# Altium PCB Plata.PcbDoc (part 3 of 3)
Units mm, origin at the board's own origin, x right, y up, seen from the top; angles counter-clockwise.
Board outline 225.2 x 126.25 mm, 5 copper layers (Top Layer, Mid-Layer 1, Mid-Layer 2, Mid-Layer 3, Bottom Layer); 204 components, 178 nets, 840 pads, 262 vias.
Unrouted connection lines stored in the file: 7.
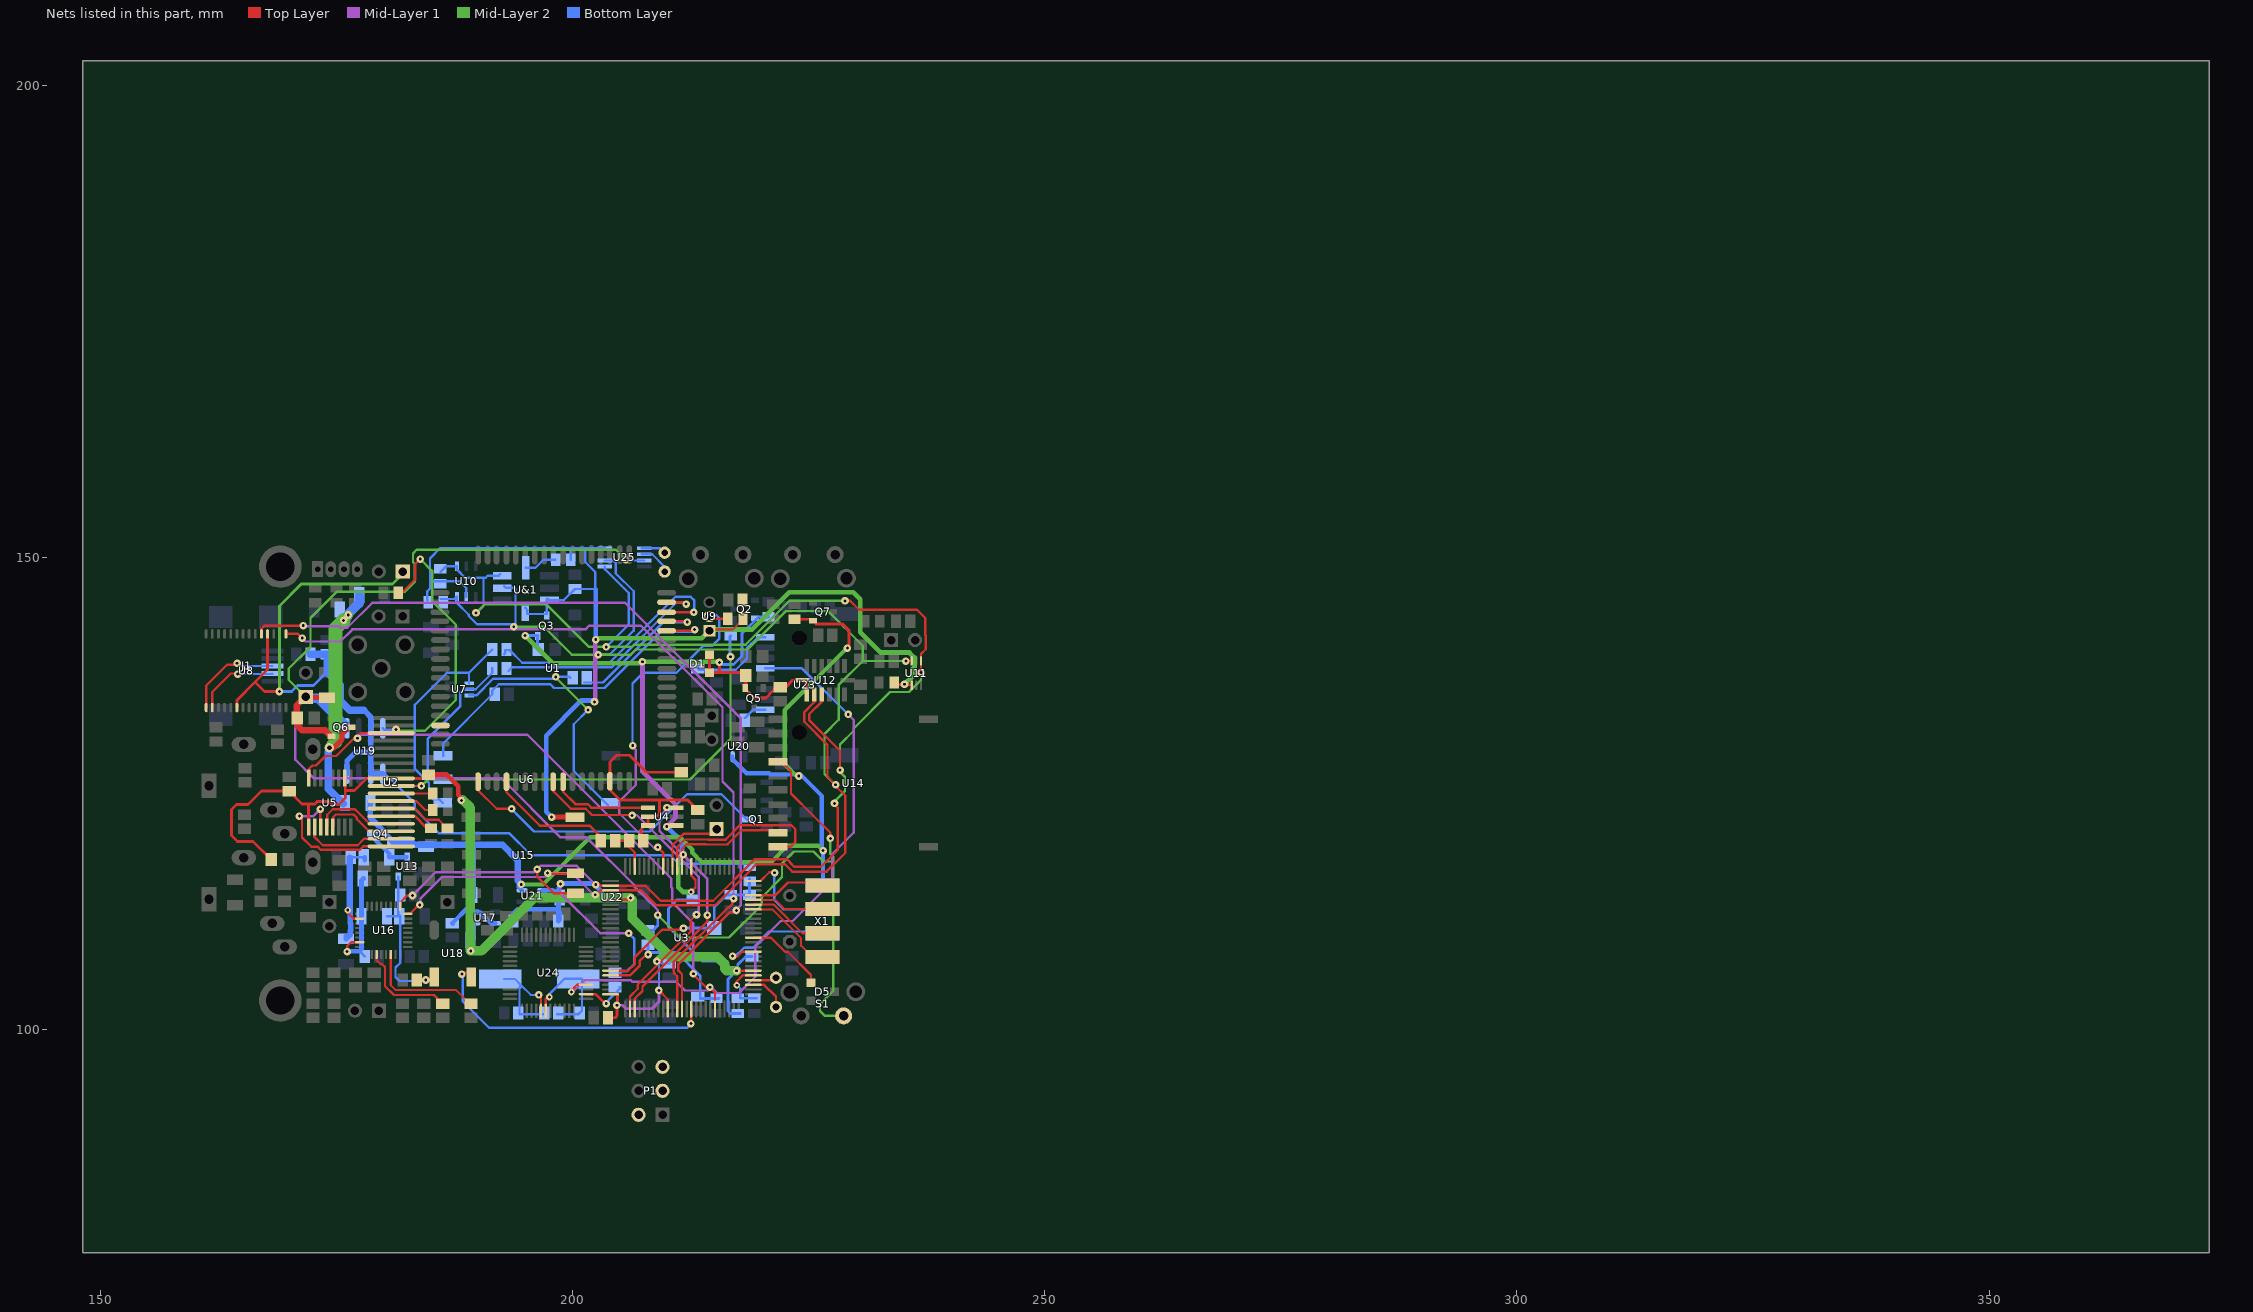
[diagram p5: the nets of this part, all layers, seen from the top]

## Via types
v1: diameter 0.8, hole 0.3, Top Layer to Bottom Layer, 158 vias
v2: diameter 0.8, hole 0.3, Top Layer to Mid-Layer 1, 69 vias
v3: diameter 0.8, hole 0.3, Mid-Layer 2 to Bottom Layer, 18 vias
v4: diameter 0.7, hole 0.3, Top Layer to Bottom Layer, 9 vias
v5: diameter 0.7, hole 0.3, Top Layer to Mid-Layer 1, 5 vias
v6: diameter 0.8, hole 0.3, Top Layer to Mid-Layer 1, tented top, 1 vias
v7: diameter 0.8, hole 0.3, Top Layer to Bottom Layer, tented top, 1 vias
v8: diameter 1, hole 0.5, Top Layer to Bottom Layer, 1 vias

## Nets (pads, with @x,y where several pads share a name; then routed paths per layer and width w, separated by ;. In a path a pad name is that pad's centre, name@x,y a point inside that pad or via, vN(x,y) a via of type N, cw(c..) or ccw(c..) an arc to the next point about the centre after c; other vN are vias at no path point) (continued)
NetR13_2: R13.2 U2.11 | length 4.4
  Top Layer w0.25: U2.11@180.8,125 R13.2@185.2,125
NetR14_2: R14.2 U2.12 | length 4.8
  Top Layer w0.25: U2.12@180.8,124.2 183.45,124.2 184.4,123.25 R14.2@185.2,123.25
NetR15_2: R15.2 U2.13 | length 6.8
  Top Layer w0.25: U2.13@180.8,123.4 183.3,123.4 184.475,122.225 185.825,122.225 R15.2@186.75,121.3
NetR16_2: R16.2 U2.14 | length 4.7
  Top Layer w0.25: U2.14@180.8,122.6 183.3,122.6 184.6,121.3 R16.2@185,121.3
NetR17_1: R17.1 U2.10 | length 49
  Top Layer w0.25: U2.10@180.8,125.8 v1(184,125.8)
  Mid-Layer 2 w0.25: v1(184,125.8) 184.675,126.475 212.425,126.475 216.725,130.775 216.725,139.175 v3@216.875,139.325
  Bottom Layer w0.3: R17.1@216.75,141.7 216.675,141.625 216.675,139.75 216.837,139.588 v3@216.95,139.475
  other v3: 216.725,139.475
NetR24_1: R24.1 U6.4 U7.6 | length 28.7
  Mid-Layer 2 w0.25: v3(198.225,137.35) 198.225,137.275 v3@201.475,134.025
  Bottom Layer w0.25: U7.6@189.04,135.39 189.815,135.39 191.575,137.15 198.125,137.15 v3@198.225,137.25 ; R24.1@199.75,137.25 199.65,137.35 v3@198.325,137.35 ; v3(201.65,133.85) 200.125,132.325 200.125,127.375 U6.4@203.75,123.75 ; v3@198.225,137.25 198.275,137.3 v3@198.325,137.35 ; v3@198.225,137.25 v3(198.225,137.35) v3@198.325,137.35
NetR26_1: R26.1 U6.3 U7.4 | length 23.7
  Bottom Layer w0.25: U6.3@186.25,124 185.85,124.4 185.225,124.4 184.8,124.825 184.8,126.096 183.3,127.596 183.3,134.4 186.69,137.79 189.04,137.79 ; U7.4@189.04,136.68 189.04,137.79 ; R26.1@191.5,140.25 189.04,137.79
NetR27_1: R27.1 U6.2 U7.5 | length 16.5
  Bottom Layer w0.25: U6.2@186.404,126.604 186.257,126.75 185.275,126.75 184.65,127.375 184.65,130.775 188.125,134.25 188.125,135.705 188.45,136.03 U7.5@189.04,136.03 189.748,136.03 191.5,137.782 R27.1@191.5,138.25
NetR29_1: R29.1 U&1.8 | length 3.5
  Bottom Layer w0.25: U&1.8@195.05,148.9 196.075,148.9 196.925,149.75 R29.1@198.2,149.75
NetR44_2: R44.2 U19.8 | length 30.5
  Top Layer w0.25: R44.2@181.55,146.25 181.95,146.25 183.325,147.625 183.325,149.275 v1(183.875,149.825)
  Mid-Layer 2 w0.25: v3@181.425,131.625 184.35,131.625 187.625,134.9 187.625,142.9 185.125,145.4 185.125,148.575 v1(183.875,149.825)
  Bottom Layer w0.25: U19.8@179.905,131.9 180.055,131.75 181.3,131.75 v3@181.525,131.75
  other v3: 181.3,131.775
NetR54_2: R54.2 U23.1 | length 2.5
  Bottom Layer w0.25: R54.2@218.25,133 219.1,133.85 U23.1@220.4,133.85
NetR55_2: R55.2 U23.8 | length 9.3
  Bottom Layer w0.25: R55.2@213.25,138.25 213.4,138.1 217.275,138.1 218.475,139.3 218.475,140.405 219.62,141.55 U23.8@220.4,141.55
NetR57_2: R57.2 U24.26 | length 5
  Top Layer w0.25: U24.26@201.425,103.75 202.425,103.75 203.375,102.8 v1@203.575,102.8 ; v1(203.575,102.758) v1@203.575,102.8 ; v1@203.8,102.8 v1@203.575,102.8
  Bottom Layer w0.25: v1@203.8,102.8 203.8,103.125 204.837,104.162 205,104.325 R57.2@205,104.5
NetU2_15: U2.15 U5.4 | length 9.5
  Top Layer w0.25: U5.4@173.932,120.9 173.932,121.425 173.957,121.45 174.025,121.517 174.025,122.75 174.6,123.325 176.962,123.325 178.487,121.8 U2.15@180.8,121.8
NetU2_16: U2.16 U5.5 | length 8.8
  Top Layer w0.25: U5.5@174.567,120.9 U5.5@174.567,121.4 ; U5.5@174.657,121.49 174.605,121.437 U5.5@174.567,121.4 ; U2.16@180.8,121 178.45,121 177.137,122.313 177.137,122.442 176.805,122.775 174.925,122.775 174.65,122.5 174.65,121.507 174.592,121.45 174.567,121.425 U5.5@174.567,121.4
NetU2_17: U2.17 U5.2 | length 9.3
  Top Layer w0.25: U5.2@172.662,120.9 172.662,120.406 173.544,119.525 177.25,119.525 177.925,120.2 U2.17@180.8,120.2
NetU2_18: U2.18 U5.3 | length 16.8
  Top Layer w0.25: v2@171.35,122.5 171.35,120.347 172.322,119.375 172.987,119.375 173.337,119.025 177.457,119.025 177.832,119.4 U2.18@180.8,119.4 ; U5.3@173.297,121.4 173.297,121.425 v2(173.297,123.347) v2@173.3,123.35
  Mid-Layer 1 w0.25: v2(171.075,122.6) 172.55,122.6 v2(173.297,123.347)
NetU3_28: U3.28 Y1.2 | length 4
  Top Layer w0.25: U3.28@219.136,104.736 220.289,104.736 221.538,103.487 Y1.2@221.538,102.387
NetU3_29: U3.29 Y1.1 | length 2.2
  Top Layer w0.25: U3.29@219.136,105.236 220.936,105.236 Y1.1@221.25,105.55
NetU25_1: U25.1 Y4.2 | length 2.6
  Bottom Layer w0.25: U25.1@207.325,150.975 U25.1@207.575,150.975 209.275,150.975 Y4.2@209.75,150.5
NetU25_2: U25.2 Y4.1 | length 3.5
  Bottom Layer w0.25: U25.2@207.325,150.325 U25.2@207.575,150.325 208.43,150.325 209.75,149.005 Y4.1@209.75,148.5
PIN1_OUT: U3.47 X1.1 | length 8.3
  Top Layer w0.22: X1.1@225.15,115.75 225.95,115.75 X1.1@226.45,115.25
  Top Layer w0.25: U3.47@219.136,114.236 220.114,114.236 ; U3.47@219.975,114.236 221.486,114.236 222.825,115.575 224.975,115.575 X1.1@225.15,115.75
PIN2_OUT: U3.44 X1.4 | length 9.9
  Top Layer w0.22: U3.44@219.136,112.736 221.133,112.736 224.2,109.669 224.2,108.875 225.375,107.7 X1.4@226.45,107.7
PIN3_OUT: U3.35 X1.7 | length 12.9
  Top Layer w0.24: v1(216.95,107.775) 217.489,107.775 217.95,108.236 U3.35@219.136,108.236
  Bottom Layer w0.24: v1@217.125,107.675 217.152,107.675 218.147,108.67 219.07,108.67 220.78,110.38 226.27,110.38 X1.7@226.45,110.2
PIN4_OUT: U3.50 X1.6 | length 11
  Top Layer w0.25: U3.50@219.136,115.736 219.911,115.736 220.825,116.65 v1@221.4,116.65
  Bottom Layer w0.25: v1@221.35,116.525 221.35,113.725 222.325,112.75 X1.6@226.45,112.75 ; v1@221.375,116.625 v1@221.4,116.65
  other v1: 221.4,116.6
POWER_ON: D5.1 U3.38 | length 8.6
  Top Layer w0.25: U3.38@219.136,109.736 220.994,109.736 222.495,108.235 222.79,108.235 225.25,105.775 D5.1@225.25,104.95
PWRKEY: Q1.3 U1.1 | length 33.8
  Top Layer w0.25: U1.1@190,126.25 190,125.35 191.975,123.375 v1(193.55,123.375)
  Bottom Layer w0.25: v1@193.637,123.237 195.9,120.975 208.175,120.975 212.125,124.925 215.775,124.925 Q1.3@218.45,122.25
RADIO_L_LINE: C29.2 U16.3 | length 10.9
  Top Layer w0.22: C29.2@185.72,102.75 C29.2@185.72,102.997
  Top Layer w0.24: U16.3@179.25,107.95 179.25,107.345 179.675,106.92 179.853,106.92 180.15,106.623 180.15,104.6 181.08,103.67 185.33,103.67 C29.2@186.25,102.75
RADIO_R_LINE: C30.2 U16.6 | length 12.6
  Top Layer w0.22: U16.6@180.75,107.95 180.75,106.85 180.75,104.7 181.275,104.175 187.675,104.175 189.1,102.75 C30.2@189.25,102.75
RESET: C1.2 P1.3 R3.1 U3.30 | length 6.6
  Top Layer w0.25: v4(217.4,104.7) 217.4,105.125 218.011,105.736 U3.30@219.136,105.736 218.196,105.736
  Bottom Layer w0.25: v4(217.4,104.7) 217.75,104.35 217.75,103.3 C1.2@219.25,103.3 C1.2@219.5,103.3
RING: R9.1 U1.4 | length 13.8
  Top Layer w0.25: U1.4@193,126.25 193,125.125 196.525,121.6 201.8,121.6 203,120.4 R9.1@203,120 R9.1@203,119.75 ; R9.1@202.695,119.805 R9.1@202.75,119.75
RING_CPU: R9.2 R10.1 U3.73 | length 4.2
  Top Layer w0.25: R9.2@204.25,119.75 R9.2@204.5,119.75 ; R9.2@204.5,120 R10.1@205.75,120 ; R10.1@206,119.75 206,119.325 206.586,118.739 U3.73@206.586,117.286
RXD_GPS: U3.63 U14.9 | length 12.9
  Top Layer w0.25: U3.63@211.586,117.286 211.586,119.119 212.087,119.62 212.154,119.62 212.164,119.631 214.112,119.631 214.138,119.605 216.362,119.605 216.377,119.62 216.423,119.62 217.903,121.1 221.5,121.1 U14.9@221.75,120.85
RXD_GSM_CPU: U1.9 U3.2 | length 37.5
  Top Layer w0.25: U1.9@197.95,126.25 197.95,125.25 199.825,123.375 201.405,123.375 202.055,122.725 v2@206.3,122.725 ; U3.2@206.086,102.186 206.086,103.13 ; 206.086,103.357 206.086,103.13 ; v2(213.125,112.175) 212.525,111.575 212.525,110.396 206.9,104.771 206.9,104.325 206.086,103.511 206.086,103.13
  Mid-Layer 1 w0.25: v2@205.975,122.725 206.3,122.725 206.8,122.725 211.21,118.315 211.21,118.303 211.957,117.556 211.969,117.556 213.35,116.175 213.35,112.425 v2@213.25,112.325
  other v2: 206.3,122.675
RXD_OUT: U3.45 X1.3 | length 8.6
  Top Layer w0.22: U3.45@219.136,113.236 221.255,113.236 221.285,113.206 221.328,113.206 224.334,110.2 X1.3@226.45,110.2
RXD_USB: U3.13 U8.5 | length 91.9
  Top Layer w0.25: U8.5@167.05,141.9 167.05,142.45 167.375,142.775 v1(171.475,142.775) ; U3.13@211.586,102.186 211.586,105.86 211.205,106.241 211.205,106.955 216.688,112.438 217.138,112.438 v2@217.138,112.625
  Mid-Layer 1 w0.25: v1(171.475,142.775) 171.6,142.65 171.65,142.7 175.279,142.7 175.429,142.55 176.15,142.55 178.8,145.2 205.561,145.2 217.825,132.936 217.825,113.175 217.525,112.875 217.525,112.625 217.525,112.45 v2@217.4,112.325
  other v2: 217.35,112.625
SCK: P1.2 U2.3 U3.20 U5.16 U23.5 U24.28 | length 134.5
  Top Layer w0.25: U5.16@172.027,126.6 172.065,126.637 U5.16@172.097,126.67 ; U5.16@172.117,126.69 U5.16@172.097,126.67 ; U2.3@180.8,131.4 177.6,131.4 177.137,130.938 176.912,130.712 176.725,130.712 174.983,128.97 173.832,128.97 172.827,127.965 172.447,127.965 172.097,127.615 U5.16@172.097,126.67 ; v5@199.775,104 199.812,104.037 200.195,104.42 200.195,104.463 200.482,104.75 U24.28@201.425,104.75 ; v2(212.8,105.91) 212.8,105.9 212.75,105.85 214.125,104.475 v1(214.55,104.475) ; v1@214.7,104.325 214.688,104.313 215.086,103.914 U3.20@215.086,102.186
  Mid-Layer 1 w0.25: v2(177.225,130.85) 177.6,131.225 195.218,131.225 210.45,115.993 210.45,115.079 210.575,114.954 210.575,113.45 212.785,111.24 212.785,105.995 212.75,105.96 212.75,105.95 212.79,105.91 v2(212.8,105.91) ; v5@199.775,104 199.875,104 200.046,104 201.253,105.207 206.188,105.207 206.325,105.07 209.974,105.07 209.979,105.075 210.621,105.075 210.626,105.07 210.962,105.07 211.897,104.135 214.36,104.135 214.625,104.4 214.775,104.4 215.3,103.875 217.632,103.875 219.35,105.593 219.35,108.772 219.675,109.097 219.675,109.128 222.047,111.5 223.318,111.5 227.5,115.682 227.5,118.582 229.775,120.857 229.775,132.77 229.22,133.325 229.19,133.368 v1@229.145,133.43 ; v5@199.775,104.075 v5@199.805,104.045
  Bottom Layer w0.25: U23.5@220.4,138.25 224.3,138.25 229.05,133.5 229.05,133.375 v1@229.05,133.25
  other v1: 229.2,133.375
  other v5: 199.875,103.975
SCL: R11.1 U3.78 U10.6 U11.6 U12.2 U15.2 U16.16 U25.6 U&1.6 | length 167.2
  Top Layer w0.25: U16.16@182.55,112.25 182.75,112.25 v2@183.512,113.012 ; v2@197.625,116.5 200.25,116.5 U15.2@200.3,116.55 ; v2(202.4,114.275) 202.429,114.275 202.579,114.425 202.65,114.425 202.961,114.736 U3.78@204.036,114.736 207.289,114.736 208.875,113.15 215.107,113.15 219.202,117.245 ; 219.206,117.241 219.49,117.525 222.472,117.525 223.272,116.725 226.9,116.725 228.875,118.7 228.875,124.775 227.825,125.825 v1@227.825,125.9 ; U12.2@225.6,135.5 225.6,134.675 224.55,133.625 224.55,132.589 227,130.139 227,126.725 v1@227.825,125.9 ; v1(227.861,125.931) 227.856,125.931 v1@227.825,125.9 ; v1@235.395,139.025 235.42,139.05 U11.6@235.9,139.05
  Mid-Layer 1 w0.25: v2(183.809,113.206) 183.894,113.206 183.9,113.2 183.9,113.206 183.9,113.875 186.175,116.15 197.125,116.15 v2@197.45,116.475 ; v2(197.35,116.575) 199.95,116.575 202.25,114.275 v2@202.25,114.15
  Mid-Layer 2 w0.25: v3(193.775,142.65) 197.021,142.65 197.021,142.608 199.929,139.7 v3(202.725,139.7) 206.15,139.7 206.7,140.25 218.532,140.25 222.607,144.325 227.037,144.325 230.721,140.64 230.721,139.025 ; v1(227.861,125.931) 227.856,125.931 227.825,125.9 226.675,127.05 226.675,131.314 228.175,132.814 228.175,136.479 230.721,139.025 ; v1@235.395,139.025 v1(235.3,139.025) 230.721,139.025
  Bottom Layer w0.25: R11.1@186.05,145.6 186.3,145.6 187.5,145.6 U10.6@187.75,145.85 187.75,145.175 189,143.925 189,143.804 189.879,142.925 193.775,142.925 v3@193.95,142.925 ; U&1.6@192.75,146.95 192.925,146.775 193.85,146.775 193.95,146.675 v3@193.95,142.925 ; v3@193.97,142.905 v3@193.95,142.925 ; v3(202.725,139.7) 203.925,139.7 206.475,142.25 206.475,146.407 204.575,148.307 204.575,149.38 204.28,149.675 U25.6@203.425,149.675
SDA: R12.1 U3.77 U10.1 U11.4 U12.3 U15.1 U16.17 U25.5 U&1.7 | length 173.2
  Top Layer w0.25: U16.17@181.75,113.05 181.75,113.475 182.475,114.2 v2(183.05,114.2) ; v2@196.245,116.975 196.245,116.205 198,114.45 U15.1@200.3,114.45 ; v2(202.45,115.35) 202.8,115.35 202.914,115.236 U3.77@204.036,115.236 207.739,115.236 209.325,113.65 214.9,113.65 219.275,118.025 222.732,118.025 223.025,117.732 223.025,117.679 223.479,117.225 226.275,117.225 228.075,119.025 228.075,123.475 227.665,123.885 v1@227.5,124.05 ; U12.3@226.4,135.5 226.4,134.75 225.05,133.4 225.05,132.796 228.325,129.521 228.325,127.575 228.275,127.525 228.225,127.475 v7@228.225,127.325 ; v1(228.85,145.4) 229.4,145.4 230.35,144.45 236.475,144.45 237.365,143.56 237.365,141.746 237.395,141.716 237.395,140.27 236.9,139.775 U11.4@236.9,139.05 v1(236.9,137.8) v1@236.9,137.6
  Mid-Layer 1 w0.25: v2(183.05,114.2) 185.5,116.65 195.925,116.65 v2@196.05,116.775 ; v2@196.461,117.211 196.6,117.35 200.425,117.35 v2@202.437,115.338
  Mid-Layer 2 w0.25: v3(189.775,144.125) 190.675,145.025 197.25,145.025 201.75,140.525 v3(203.575,140.525) 206.268,140.525 206.493,140.75 218.325,140.75 223,145.425 228.625,145.425 228.75,145.3 v1@228.85,145.2 ; v1@227.675,124.1 228.85,125.275 228.85,126.75 v7@228.225,127.375 ; v7@228.325,127.325 v7(228.325,127.475) 228.325,130.2 229.775,131.65 229.775,131.896 233.629,135.75 235.625,135.75 236.9,137.025 v1(236.9,137.8)
  Bottom Layer w0.25: R12.1@186.05,148.5 186.175,148.625 186.6,149.05 U10.1@187.75,149.05 187.75,148.725 188.625,147.85 190.8,147.85 191.025,148.075 192.175,148.075 U&1.7@192.35,148.25 ; v3@189.85,144.125 190.575,144.85 190.575,147.825 ; U25.5@203.425,149.025 203.425,148.75 205.95,146.225 205.95,142.9 v3(203.575,140.525)
  other v1: 227.736,123.956
  other v2: 196.25,116.975
SIM_CLK: R26.2 U1.32 | length 28.2
  Top Layer w0.25: U1.32@209.95,144.2 v1@212.75,144.2
  Bottom Layer w0.25: R26.2@192.762,139.763 192.875,139.875 192.875,140.2 193,140.2 193.325,140.2 194.675,138.85 203.925,138.85 210.9,145.825 212.504,145.825 212.9,145.429 212.9,144.33 212.798,144.227 v1@212.77,144.2
  other v1: 212.825,144.2
SIM_DATA: R24.2 U1.31 | length 15.7
  Top Layer w0.25: U1.31@209.95,143.25 v1@212.125,143.25
  Bottom Layer w0.25: R24.2@201.25,136.75 201.5,136.75 203.239,136.75 209.639,143.15 v1(212.15,143.15)
SIM_RESET: R27.2 U1.33 | length 23.9
  Top Layer w0.25: U1.33@209.95,145.25 212.025,145.25 212.01,145.235 v1@212.01,145.207
  Bottom Layer w0.25: R27.2@193.25,138 193.6,138.35 204.132,138.35 211.032,145.25 211.967,145.25 v1@212.01,145.207
  other v1: 212.025,145.05
SIM_VDD: C13.2 U1.30 U6.1 | length 36.2
  Top Layer w0.25: U1.30@209.95,142.25 v1@212.925,142.25
  Bottom Layer w0.25: U6.1@186.3,129 186.3,130.3 191.5,135.5 191.5,135.9 192.175,136.575 197.65,136.575 198.05,136.175 203.371,136.175 209.296,142.1 v1@212.8,142.1
  other v1: 212.925,142.35
STATUS: U1.66
TEMP: R28.2 U3.67 U9.2 | length 39.1
  Top Layer w0.25: v1(209.025,119.3) 209.586,118.739 U3.67@209.586,117.286 ; U9.2@214.5,144 214.625,143.875 215,143.5 R28.2@216.45,143.5
  Mid-Layer 1 w0.25: v1@206.25,130.1 206.325,130.025 206.7,129.65 206.7,125.9 204.95,124.15 204.95,122.907 208.657,119.2 v1@208.925,119.2
  Bottom Layer w0.25: v1@206.35,130.075 206.35,136.65 207.475,137.775 210.975,137.775 213.825,140.625 214.775,140.625 215.55,141.4 215.55,143.55 215.1,144 U9.2@214.5,144
  other v1: 206.375,130.075
TXD_GPS: U3.64 U14.10 | length 19.1
  Top Layer w0.25: U3.64@211.086,117.286 211.086,119.326 211.88,120.12 211.946,120.12 211.957,120.131 214.319,120.131 214.345,120.105 216.155,120.105 216.17,120.12 216.216,120.12 217.746,121.65 223.15,121.65 223.575,121.225 223.575,119.85 223.075,119.35 U14.10@221.75,119.35
TXD_GSM: U1.10 U4.4 | length 10.8
  Top Layer w0.25: U1.10@199,126.25 199,125.175 200.3,123.875 201.612,123.875 201.987,123.5 U4.4@208,123.5
TXD_GSM_CPU: U3.3 U4.3 | length 28
  Top Layer w0.25: 206.586,103.193 U3.3@206.586,102.186 206.586,103.286 207.4,104.1 207.4,104.564 214.275,111.439 v2(214.275,112.125)
  Mid-Layer 1 w0.25: v2(210,123.5) 210,123.35 209.2,122.55 209.2,121.032 211.71,118.522 211.71,118.51 212.164,118.056 212.176,118.056 214.275,115.957 v2(214.275,112.125) v2@214.275,112.025
TXD_OUT: U3.46 X1.2 | length 7.7
  Top Layer w0.22: U3.46@219.136,113.736 221.42,113.736 221.48,113.676 221.522,113.676 222.448,112.75 X1.2@226.45,112.75
TXD_USB: U3.12 U8.1 | length 86
  Top Layer w0.25: U8.1@169.65,141.9 170.925,141.9 v1(171.375,141.45) ; U3.12@211.086,102.186 211.086,105.653 210.705,106.034 210.705,107.162 216.481,112.938 216.563,112.938 216.9,113.275 v2@216.9,113.875
  Mid-Layer 1 w0.25: v1(171.375,141.45) 171.725,141.1 175.407,141.1 176.682,142.375 201.358,142.375 201.758,142.775 207.23,142.775 215.875,134.13 215.875,126.275 217.05,125.1 v2(217.05,113.875)
U_BAT_CONTROL: C11.2 R21.2 R25.1 U3.96 | length 17
  Top Layer w0.25: U3.96@204.036,105.736 206.093,105.736 207.1,106.743 207.1,107.25 v1@207.75,107.9
  Bottom Layer w0.3: R21.2@208,109 v1(208,107.95) 208.2,108.15 211.05,108.15 213.525,105.675 213.525,103.5 213.525,103.275 215.25,103.275 215.475,103.275 R25.1@215.525,103.325
U_IN_CONTROL: C61.1 D4.2 R46.1 R49.2 U3.95 | length 21.6
  Top Layer w0.25: U3.95@204.036,106.236 205.886,106.236 206.6,106.95 206.6,107.7 209.475,110.575 v1@211.75,110.575
  Top Layer w0.3: v1@211.75,110.575 v1@211.9,110.575
  Bottom Layer w0.3: v1@211.75,110.75 D4.2@215,110.75 215,112.975 216.275,114.25 216.75,114.25 C61.1@218.75,114.25 R46.1@218.75,115.7 R46.1@218.75,115.95
  other v1: 211.75,110.725
USB+: J1.3 U8.15 | length 10.4
  Top Layer w0.25: U8.15@161.2,134.1 161.2,136.425 163.425,138.65 v1@164.475,138.65
  Bottom Layer w0.25: v1(164.475,138.8) 164.775,138.5 J1.3@168.213,138.5
USB-: J1.2 U8.16 | length 8.7
  Top Layer w0.25: U8.16@161.85,134.1 161.85,135.75 163.8,137.7 v1@164.425,137.7
  Bottom Layer w0.25: v1(164.525,137.65) 168.163,137.65 J1.2@168.213,137.7
VBAT: BT1.1 C62.1 Q6.2 R21.1 R43.1 S1.2 U14.4 U19.5 U25.3 | length 179.5
  Top Layer w0.25: U14.4@221.75,128.35 222.13,128.35 223.125,127.355 223.125,125.012 ; 223.2,124.937 223.125,125.012 ; v1(227.3,120.25) 227.3,120.844 225.494,122.65 225.487,122.65 223.125,125.012
  Top Layer w0.3: R43.1@170.8,132.95 170.725,132.875 170.85,132.75 170.85,132.2
  Top Layer w0.55: BT1.1@171.75,135.23 171.83,135.15 C62.1@174,135.15
  Top Layer w0.7: R43.1@170.8,132.95 170.8,133 170.8,134.35 171.575,135.125 171.575,135.23 BT1.1@171.575,135.275 ; 170.85,132.2 171.37,131.68 173.82,131.68 Q6.2@174.45,131.05
  Mid-Layer 1 w0.25: BT1.1@171.75,135.23 170.65,134.13 170.65,128.572 172.522,126.7 ; 172.66,126.605 192.484,126.605 198.739,120.35 201.478,120.35 206.6,115.228 206.6,115.075 209.025,112.65 v1(209.025,112.125)
  Mid-Layer 1 w0.3: 172.522,126.7 172.565,126.7 172.66,126.605
  Mid-Layer 2 w0.25: BT1.1@171.75,135.23 169.95,137.03 169.95,138.22 172.25,140.52 172.25,143.6 175,146.35 182.225,146.35 183.275,147.4 183.275,149.329 183.1,149.504 183.1,150.425 183.5,150.825 204.575,150.825 v3(205.65,149.75) ; v1(209.025,112.125) 211.4,109.75 216.571,109.75 220.025,113.204 220.025,114 222.175,116.15 222.175,117.575 223.457,118.857 225.522,118.857 226.579,117.8 227.625,117.8 ; v1(227.3,120.25) 227.3,118.629 227.625,118.304 227.625,117.8 ; 227.6,104.354 227.6,104.1 ; S1.2@228.7,101.45 226.725,101.45 226.2,101.975 226.2,102.7 227.6,104.1 ; 227.6,104.1 227.625,104.125 227.625,117.8
  Bottom Layer w0.25: v3(205.65,149.75) 205.725,149.675 U25.3@207.575,149.675
  Bottom Layer w0.3: 175.625,131.9 175.925,131.9 U19.5@176.095,131.9 ; R21.1@208,110.5 208.5,110.5 209.025,111.025 v1(209.025,112.125)
  Bottom Layer w1: BT1.1@171.975,135.075 173.075,135.075 175.925,132.225 U19.5@175.925,131.9
VCC3: C5.1 C14.1 C22.2 C23.2 C24.2 C31.1 C51.2 D1.1 D1.2 P1.4 Q2.2 Q3.2 Q5.2 R3.2 R22.2 R31.1 R38.1 R40.1 R53.1 U2.9 U3.10 U3.31 U3.61 U3.80 U3.100 U4.1 U5.1 U5.10 U12.1 U12.14 U17.3 | length 222.5
  Top Layer w0.25: U3.100@204.036,103.736 204.539,103.736 204.75,103.525 ; U3.80@204.036,113.736 v1@206.15,113.736 ; v1(209.15,104.15) 210.086,103.214 U3.10@210.086,102.186 ; v1@209.975,121.6 U4.1@211,121.6 ; v4(212.55,114.575) 213.025,115.05 213.025,115.85 212.586,116.289 U3.61@212.586,117.286 ; 217.786,106.236 U3.31@219.136,106.236
  Top Layer w0.3: R40.1@168.1,118 166.175,119.925 164.5,119.925 163.875,120.55 163.875,123.3 164.4,123.825 165.625,123.825 167.05,125.25 C14.1@170,125.25 171.35,123.9 172.4,123.9 ; U5.1@172.027,120.9 172.027,121.425 172.027,123.827 ; 172.044,123.9 172.719,123.9 172.966,124.147 174.196,124.147 174.494,123.85 175.25,123.85 175.925,124.525 175.925,125.2 ; U5.10@175.925,126.512 175.925,125.2 ; U2.9@178.494,126.6 U2.9@180.8,126.6 ; C5.1@184.75,127 184.35,126.6 U2.9@180.8,126.6 ; R53.1@203.75,101.25 204.525,101.25 204.7,101.425 v2(204.7,102.575) ; v2@204.75,102.85 204.75,103.525 ; D1.2@214.5,139.7 D1.1@214.5,137.8 215.55,137.8 ; v1(215.55,138.875) 215.55,137.8 ; R38.1@218.175,137.675 218.05,137.8 215.55,137.8 ; R38.1@218.35,137.5 218.35,136.15 218.35,136.1 218.3,136.05 219.25,135.1 220.498,135.1 220.87,135.472 220.87,135.52 221.6,136.25 C31.1@222,136.25 222.575,136.25 223.325,137 U12.14@224.35,137 224.8,136.55 U12.1@224.8,135.5 ; 175.925,125.2 176.05,125.325 176.9,125.325 178.175,126.6 U2.9@180.8,126.6
  Top Layer w0.5: C5.1@184.75,127 186.657,127 187.9,125.757 187.9,124.875 v1@188.363,124.412
  Mid-Layer 1 w0.3: v2(204.7,102.575) 205.3,102.575 205.675,102.2 208.4,102.2 209.15,102.95 v1(209.15,104.15)
  Mid-Layer 1 w0.5: v1(207.4,138.95) 207.4,127.33 210.33,124.4 ; v1(209.975,121.5) 210.9,122.425 210.9,123.873 210.373,124.4
  Mid-Layer 2 w0.5: v3(194.975,141.725) 197.9,138.8 207.25,138.8 v1(207.4,138.95) v1@215.53,138.95 ; v3(211.725,118.525) 211.2,118 211.2,115.05 211.675,114.575 v4(212.55,114.575)
  Mid-Layer 2 w0.8: v3(208.925,107.225) 209.75,108.05
  Mid-Layer 2 w1: v1@188.313,124.362 189.175,123.5 189.175,108.325 v1(189.225,108.325) 190.35,108.325 195.975,113.95 v1@206.125,113.95 ; v1@206.314,113.736 206.314,111.761 210.455,107.62 210.535,107.7 215.351,107.7 216.1,106.951 216.1,106.45 216.3,106.25 v1@217.375,106.25
  Bottom Layer w0.25: v1(209.15,104.15) 209.15,106.825 ; 209.325,107 C24.2@210.25,107
  Bottom Layer w0.3: C51.2@189.15,109.75 C51.2@189.4,110 ; v3(194.975,141.725) 196.3,141.725 Q3.2@196.325,141.725 ; R31.1@196.3,140.3 Q3.2@196.3,141.7 ; C22.2@212.75,113.75 211.075,113.75 210.15,112.825 210.15,110.85 213.73,107.27 215.944,107.27 v1@217.039,106.175 ; v1@215.675,138.85 215.85,138.675 217.056,138.675 217.95,139.569 217.95,141.975 219.412,143.437 219.675,143.7 R22.2@220.75,143.7 ; v1@217.375,106.25 217.362,106.237 216.45,105.325 216.45,101.975 216.725,101.7 R3.2@217.5,101.7 R3.2@217.75,101.7 ; v1@217.5,106.25 217.5,106.875 218.375,107.75 C23.2@219,107.75
  Bottom Layer w0.5: v1(209.975,121.5) 211.595,119.88 v3@211.595,118.525
  Bottom Layer w0.7: C51.2@189.4,110 U17.3@189.4,111.25
  other v1: 217.375,106.225 206.15,113.95 188.225,124.275
VCC3_A: C32.1 C35.1 L4.2 U16.31 | length 11.6
  Top Layer w0.25: v1@176.15,108.425 176.15,108.85 176.55,109.25 U16.31@177.45,109.25
  Bottom Layer w0.25: 177.45,108.3 177.65,108.5 ; L4.2@177.5,112 177.575,111.925 L4.2@177.65,111.85 ; C35.1@177.65,108.1 C35.1@178,107.75
  Bottom Layer w0.5: v1@176.237,108.363 176.3,108.3 177.45,108.3 ; 177.65,108.5 L4.2@177.65,111.85 ; L4.2@177.65,112 177.65,115.8 177.813,115.962 C32.1@177.85,116
  other v1: 176.125,108.25
VCC3_ACPU: C26.2 C57.1 L3.1 L4.1 U13.2 U18.4 | length 17.4
  Top Layer w0.22: C57.1@183.5,105.25 v1(184.45,105.25) 184.758,105.25 U18.4@185.095,105.587
  Bottom Layer w0.25: L4.1@180.35,112 L3.1@181.65,112 L3.1@181.75,112 ; U13.2@181.55,116.2 181.55,114.25 181.55,112.2 181.7,112.05 L3.1@181.75,112 ; v1@184.4,105.15 181.678,105.15 181.255,105.573 181.255,106.559 181.75,107.054 L3.1@181.75,112
VCC3_I2C: C20.1 C21.2 Q3.3 R11.2 R12.2 R28.1 R29.2 R32.2 U9.1 U10.5 U11.1 U15.5 U25.8 U&1.3 U&1.4 | length 126
  Top Layer w0.22: U9.1@214.5,142.5 214.625,142.375 214.65,142.35 216.959,142.35 218.05,143.441 R28.1@218.05,143.5 ; R28.1@218,143.5 C20.1@218,145
  Top Layer w0.25: v1@197.575,122.5 v1(197.775,122.5) ; R32.2@234.55,136.5 235.15,136.5 235.85,136.5 U11.1@235.9,136.45
  Top Layer w0.5: v1(197.775,122.5) U15.5@200.25,122.5
  Mid-Layer 1 w0.25: v1(202.325,134.7) v1@202.4,134.775
  Mid-Layer 1 w0.5: v1@202.4,134.775 v1@202.4,141.175
  Mid-Layer 2 w0.3: U9.1@214.5,142.25 U9.1@214.5,142.5
  Mid-Layer 2 w0.5: v1@202.4,141.4 202.45,141.4 202.5,141.45 213.7,141.45 U9.1@214.5,142.25 ; U9.1@214.675,141.95 214.738,142.013 215.1,142.375 219.025,142.375 222.17,145.52 222.95,146.3 229.725,146.3 230.475,145.55 230.475,142.075 232.655,139.895 232.685,139.925 235.673,139.925 236.2,139.398 236.2,138.373 236,138.173 236,137.425 v1(235.15,136.575)
  Bottom Layer w0.25: R11.2@184.625,145.475 184.625,146.425 184.9,146.7 184.9,147.482 ; U10.5@188.75,145.85 188.75,146.725 187.993,147.482 186,147.482 184.9,147.482 ; U&1.4@195,144.65 195.2,144.45 195.2,144.25 195.2,144 197.25,144 197.25,145.45 197.25,145.55 197.35,145.65 197.525,145.475 197.55,145.475 199.075,145.475 C21.2@200.25,146.65 202.4,146.65 ; R29.2@199.8,149.75 199.8,150.85 199.675,150.975 ; 202.45,146.6 202.4,146.65 ; U25.8@203.425,150.975 201.35,150.975 ; 184.9,147.482 184.9,149.9 185.975,150.975 199.675,150.975 ; 199.675,150.975 201.35,150.975 ; 201.35,150.975 201.35,149.5 202.4,148.45 202.4,146.65
  Bottom Layer w0.5: v1(197.775,122.5) 197.2,123.075 197.2,131.125 200.925,134.85 202.175,134.85 v1(202.325,134.7) ; v1(202.45,141.3) 202.45,146.6
VCC3_MP3: C64.1 L7.2 L9.2 R57.1 U21.3 U22.3 | length 33.1
  Mid-Layer 1 w0.25: v1(198.725,115.425) 198.725,114.425 202.95,110.2 v1(205.95,110.2)
  Bottom Layer w0.25: R57.1@205,106 205.15,106.15 205.721,106.15 206.55,106.979 206.55,109.6 206.012,110.137 v1@206.075,110.2
  Bottom Layer w0.5: L7.2@193.75,111.5 193.75,112.305 194.195,112.75 198.3,112.75 198.5,112.55 ; U21.3@196.85,114.75 197.9,114.75 C64.1@198.55,114.1 ; 198.55,115.025 C64.1@198.55,114.1 ; v1@199,115.475 202.2,115.475 203.1,114.575 203.1,114.2 203.225,114.075 U22.3@203.3,114 ; 198.5,112.55 L9.2@198.5,111.5 198.625,111.625 198.625,112.425 198.5,112.55 ; 198.5,112.55 198.5,113.85 C64.1@198.65,114 C64.1@198.55,114.1
VCC_A: C33.1 C36.1 L5.2 U16.26 | length 12.3
  Top Layer w0.25: v4@176.2,112.35 176.8,111.75 U16.26@177.45,111.75
  Bottom Layer w0.25: C36.1@176.5,118.25 L5.2@177.9,118.25 L5.2@178,118.25
  Bottom Layer w0.5: C36.1@176.425,118.175 C36.1@176.5,118.25 ; L5.2@178,117.957 L5.2@178,118.25
  Bottom Layer w0.55: C33.1@176,109.6 C33.1@176.475,110.075 ; C33.1@176,109.85 C33.1@176.042,109.892 ; 176.425,112.925 176.45,112.9 176.475,112.875 v4@176.475,112.65
  Bottom Layer w0.6: C33.1@176.475,110.075 176.475,110.452 176.5,110.477 176.5,111.223 176.475,111.248 v4@176.475,112.65
  Bottom Layer w0.7: 176.425,112.925 C36.1@176.425,118.175
  other v4: 176.2,112.65
VCC_ACPU: L5.1 Q4.3 U13.3 | length 5
  Bottom Layer w0.25: U13.3@182.4,118.25 U13.3@182.5,118.35
  Bottom Layer w0.45: 179.15,120.75 179.15,120.05 L5.1@180.6,118.6
  Bottom Layer w0.5: L5.1@180.6,118.6 L5.1@180.6,118.25 U13.3@182.4,118.25
VCC_BATT: C47.2 C48.1 C56.1 L6.2 Q4.2 Q7.2 R34.1 R50.1 U17.2 U17.4 U20.2 U21.2 X1.5 | length 117.6
  Top Layer w0.25: R50.1@223.5,143.45 225.3,143.45 Q7.2@225.45,143.3
  Top Layer w0.35: Q7.2@225.45,143.3 225.8,142.95 228.55,142.95 229.275,142.225 229.275,140.575 v1(229.1,140.4)
  Mid-Layer 2 w0.45: v1(194.575,115.375) 196.875,115.375 201.875,120.375 211.375,120.375 212.675,119.075 212.675,118.737 213.662,117.75 221.05,117.75 222.775,119.475 226,119.475 v3(226.525,118.95) 226.55,118.95 v3@226.575,118.975 ; v1@223.625,126.95 222.475,128.1 222.475,133.825 v1@229,140.35
  Bottom Layer w0.45: Q4.2@181.031,119.844 181.223,119.844 Q4.2@181.225,119.825 ; R34.1@182.925,119.825 R34.1@182.945,119.873 ; C48.1@187.3,111.2 C48.1@187.25,111.25 188.95,112.95 189.4,112.95 ; C47.2@189.4,114 189.4,112.95 ; U17.2@191.85,111.25 191.375,111.25 190.175,112.45 U17.4@189.65,112.45 189.4,112.7 189.4,112.95 ; 194.185,115.765 194.3,115.65 194.3,115.375 194.3,115.1 U21.2@194.65,114.75 ; U20.2@216.95,128.887 216.95,128.625 218.425,127.15 220.125,127.15 220.799,127.15 220.949,127 223.95,127 224.125,127 226.4,124.725 226.4,119.075 v3(226.525,118.95) 226.525,115.325 X1.5@226.45,115.25
  Bottom Layer w0.6: L6.2@178.6,124 178.571,123.971 178.571,122.425 179.925,121.071 ; 179.925,120.95 180.938,119.937 Q4.2@181.031,119.844
  Bottom Layer w0.7: Q4.2@181.225,119.825 182.25,119.825 182.925,119.825 183,119.825 ; 182.975,119.575 184.5,119.575 189.4,119.575 ; C47.2@189.4,114 C47.2@189.4,114.25 189.4,119.575 ; 189.4,119.125 189.4,119.575 ; 194.185,115.765 194.185,117.973 192.583,119.575 189.4,119.575
  other v1: 223.95,126.85
VCC_GSM: C59.1 L1.1 L6.1 Q6.3 | length 27
  Top Layer w0.55: v8@174.624,129.756 175.575,130.708 175.575,131.3 176.275,132 Q6.3@176.6,132
  Mid-Layer 2 w1: v1@175.75,143.4 v1(176.25,143.9)
  Mid-Layer 2 w1.2: v8@174.475,130.1 174.9,130.525
  Mid-Layer 2 w1.5: 174.9,130.525 174.9,142.475 v1(175.75,143.325)
  Bottom Layer w0.8: v8@174.15,129.4 174.15,125.5 L6.1@175.725,123.925
  Bottom Layer w1: v1(175.75,143.325) v1@176.25,143.825 ; v1@176.225,143.975 177.4,145.15 L1.1@177.4,145.925
  other v8: 174.25,129.85
VCC_USB: C18.2 D3.1 L2.2 R46.2 U8.4 U8.20 U19.1 U19.2 U19.4 U19.7 | length 107.8
  Top Layer w0.3: U8.20@164.45,134.1 164.45,134.875 166.382,136.807 ; U8.4@167.7,141.9 167.7,138.125 166.382,136.807 ; v1(168.95,135.8) 167.39,135.8 166.382,136.807
  Mid-Layer 2 w0.3: v1(168.95,135.8) 168.95,144.85 171.275,147.175 180.945,147.175 182.145,148.375 D3.1@182.27,148.5
  Bottom Layer w0.25: U19.1@179.905,127.1 179.93,127.075 180.155,127.075 183.3,123.93 183.3,123.325 185.825,120.8 193.275,120.8 195.625,118.45 210.35,118.45 211.25,117.55 R46.2@218.75,117.55
  Bottom Layer w0.3: v1(168.95,135.8) 170.254,135.8 170.904,136.45 172.575,136.45 173.975,137.85 174,137.85
  Bottom Layer w0.55: U19.4@176.095,127.1 176.095,127.935 176.1,127.94 176.1,128.475 177,129.375 178.635,129.375 ; U19.7@178.635,131.9 178.635,129.375 ; U19.1@179.905,127.1 U19.2@178.635,127.1 178.635,129.375
  Bottom Layer w0.6: 177.9,133.825 178.635,133.09 U19.7@178.635,131.9
  Bottom Layer w0.8: L2.2@172.25,139.75 C18.2@174,139.75 174,137.85 175.4,136.45 175.4,134.825 176.4,133.825 177.9,133.825
VDD_EXT: C6.2 R10.2 R18.2 U1.15 U4.5 U4.6 | length 27.6
  Top Layer w0.3: R10.2@207.25,119.75 207.25,120 207.25,121.2 U4.6@207.65,121.6 ; U4.6@208,121.6 U4.5@208,122.55 208.9,122.55 209.2,122.85 209.2,124.3 ; R18.2@211.5,127.25 207.675,127.25 207.675,127.406 206.031,129.05 204.675,129.05 203.95,128.325 U1.15@203.95,126.3 203.95,125.375 205.025,124.3 209.2,124.3 ; C6.2@213.25,123.25 212.2,124.3 209.2,124.3
VIB: LS1.1 U3.65 | length 7.6
  Top Layer w0.22: U3.65@210.586,117.286 210.586,119.469
  Top Layer w0.24: 210.586,119.469 210.586,119.526 211.81,120.75 214.77,120.75 LS1.1@215.25,121.23
ZQ_ACPU_ON: U3.15 U18.1 | length 31
  Top Layer w0.25: v1@188.275,106.025 188.844,106.025 U18.1@189.282,105.587 ; U3.15@212.586,102.186 212.586,100.714 212.6,100.7 v1@212.675,100.625
  Bottom Layer w0.25: v1@188.375,105.8 188.375,102.975 191.175,100.175 212.125,100.175 212.338,100.388 v1@212.525,100.388
  other v1: 212.525,100.625 188.275,105.875
ZQ_MP3: C72.1 R58.1 U24.18 Y3.1 | length 12
  Top Layer w0.25: U24.18@197.15,101.975 197.15,103.225 v4@197.425,103.5
  Bottom Layer w0.25: v4@197.5,103.725 199.15,105.375 Y3.1@200.62,105.375 200.995,105.375 200.995,101.995 C72.1@200.75,101.75 200.625,101.625 198.5,101.625 R58.1@198.375,101.625
  other v4: 197.55,103.45
ZQ_MP3_1: C73.1 R58.2 U24.17 Y3.2 | length 11.6
  Top Layer w0.22: U24.17@196.65,101.975 v1@196.65,103.5
  Bottom Layer w0.22: Y3.2@192.74,105.375 193.875,105.375 Y3.2@194.538,104.712 ; v1(196.425,103.675) 195.575,103.675 Y3.2@194.538,104.712 ; R58.2@196.875,101.625 194.375,101.625 194.375,101.75 194.375,104.55 Y3.2@194.538,104.712
pads on no net: J1.4 J2.3 J3.3 S1.3 S1.4 S2.3 S2.4 S3.3 S3.4 U1.2 U1.3 U1.5 U1.6 U1.7 U1.8 U1.11 U1.12 U1.13 U1.14 U1.22 U1.23 U1.24 U1.25 U1.27 U1.28 U1.35 U1.36 U1.37 U1.38 U1.40 U1.41 U1.42 U1.43 U1.44 U1.47 U1.48 U1.49 U1.50 U1.51 U1.67 U1.68 U3.5 U3.7 U3.8 U3.9 U3.14 U3.16 U3.17 U3.18 U3.19 U3.23 U3.27 U3.37 U3.41 U3.42 U3.51 U3.55 U3.59 U3.70 U3.71 U3.72 U3.79 U3.82 U3.83 U3.84 U3.85 U3.86 U3.87 U3.88 U3.89 U3.90 U3.91 U3.92 U3.94 U5.7 U5.8 U5.9 U5.13 U6.5 U7.1 U7.3 U8.2 U8.3 U8.6 U8.8 U8.9 U8.10 U8.11 U8.12 U8.13 U8.14 U8.19 U8.22 U8.23 U8.24 U8.27 U8.28 U10.3 U10.4 U12.4 U12.5 U12.8 U12.9 U14.2 U14.5 U14.6 U14.7 U15.4 U15.9 U16.4 U16.5 U16.9 U23.0 U23.GND U24.2 U24.9 U24.10 U24.15 U24.25 U24.27 U24.39 U24.42 U24.46 U25.7 U&1.2 U&1.5
copper on no net: | length 11
  Bottom Layer w0.24: 231.2,144 231.3,144.1
  Bottom Layer w0.5: 228.8,130.575 228.8,129.05 ; 228.8,142.225 228.8,144 230.811,144 ; 229.55,127.6 228.8,128.35 228.8,129.05 ; 230.225,145.35 230.225,145.125 230.811,144.539 230.811,144 ; 230.6,129.025 230.575,129.05 228.8,129.05 ; 231.2,144 230.811,144

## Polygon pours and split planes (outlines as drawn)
AGND on Top Layer "Top Layer-No Net" (solid, remove dead copper, pour order 1000): 159.85,130.025 173.314,130.025 173.314,124.9 181.238,116.675 181.527,116.375 186.2,116.375 186.2,100.625 186.152,100.575 186.08,100.5 159.85,100.5
GND on Top Layer "Top Layer-No Net" (solid, remove dead copper, pour order 1000): 160.116,144.725 160.141,144.7 167.241,144.7 167.241,151.55 167.266,151.525 231.066,151.525 231.066,144.95 231.141,144.875 237.591,144.875 237.591,133.225 237.566,133.25 231.016,133.25 231.016,119.875 231.041,119.85 231.066,119.825 237.691,119.825 237.716,119.8 237.716,117.875 228.616,117.875 228.491,117.75 228.491,105.275 231.016,105.275 231.041,105.25 231.041,100.125 167.191,100.125 167.166,100.1 167.141,100.125 167.141,107.125 160.116,107.125 160.091,107.15
GND1 on Top Layer "Top Layer-No Net" (solid, remove dead copper, pour order 1000): 207.5,137.15 207.55,137.1 207.55,126.8 217.675,126.8 217.925,127.05 218.025,127.15 218.025,137.15
A_CPU_ON on Top Layer "Top Layer-No Net" (solid, pour order 1000): 188.1,140.725 188.45,140.375 203.425,140.375 203.425,128.6 203.85,128.175 203.225,128.8 187.95,128.8
AGND on Bottom Layer "Top Layer-No Net" (solid, remove dead copper, pour order 1001): 159.85,130.025 173.314,130.025 173.314,124.9 181.238,116.675 181.527,116.375 186.2,116.375 186.2,100.625 186.152,100.575 186.08,100.5 159.85,100.5
GND on Bottom Layer "Top Layer-No Net" (solid, remove dead copper, pour order 1001): 160.009,144.67 160.034,144.645 167.134,144.645 167.134,151.495 167.159,151.47 230.959,151.47 230.959,144.895 231.034,144.82 237.484,144.82 237.484,133.17 237.459,133.195 230.909,133.195 230.909,119.82 230.934,119.795 230.959,119.77 237.584,119.77 237.609,119.745 237.609,117.82 228.509,117.82 228.384,117.695 228.384,105.22 230.909,105.22 230.934,105.195 230.934,100.07 167.084,100.07 167.059,100.045 167.034,100.07 167.034,107.07 160.009,107.07 159.984,107.095
GND1 on Bottom Layer "Top Layer-No Net" (solid, remove dead copper, pour order 1001): 207.551,137.157 207.601,137.107 207.601,126.807 217.726,126.807 217.976,127.057 218.076,127.157 218.076,137.157
AGND on Mid-Layer 1 "Top Layer-No Net" (solid, remove dead copper, pour order 1001): 160.7,130.025 173.73,130.025 173.73,124.9 181.398,116.675 181.678,116.375 186.2,116.375 186.2,100.625 186.153,100.575 186.083,100.5 160.7,100.5
AGND on Mid-Layer 1 "Top Layer-No Net" (solid, remove dead copper, pour order 1000): 160.724,130.025 160.7,130.05 160.7,140.925 176.845,140.925 177.059,140.7 177.225,140.525 177.225,134.525 177.225,130.65 176.584,129.975
GND on Mid-Layer 2 "Top Layer-No Net" (solid, remove dead copper, pour order 1001): 160.625,150.928 160.698,150.853 230.075,150.853 230.075,136.976 225.842,132.616 225.769,132.542 225.769,121.206 225.769,100.602 225.576,100.403 225.527,100.453 160.722,100.453

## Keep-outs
Keep-Out Layer:
  lines w0.25: 166.95,144.9 159.95,144.9 159.95,107.05 166.975,107.05 166.975,99.675 231.175,99.675 231.175,105.45 228.65,105.45 228.65,117.75 237.65,117.75 ; 167.05,145 167.05,151.75 231.145,151.75 231.192,145.075 237.9,145.075 237.9,117.625

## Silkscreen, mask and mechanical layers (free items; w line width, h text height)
Mechanical 4:
  lines w0.25: 159.95,107.05 166.975,107.05 166.975,99.55 231.175,99.55 231.175,105.45 228.75,105.45 228.75,117.75 237.65,117.75 237.9,117.5 237.9,145.075 231.192,145.075 231.145,151.75 167.05,151.75 167.05,145 166.95,144.9 159.95,144.9 159.95,107.05 ; 177.05,119.075 177.05,129.575 177.05,133.5 182.5,133.5 182.5,119.075 177.05,119.075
